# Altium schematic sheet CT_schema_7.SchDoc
size 371 x 245 mm
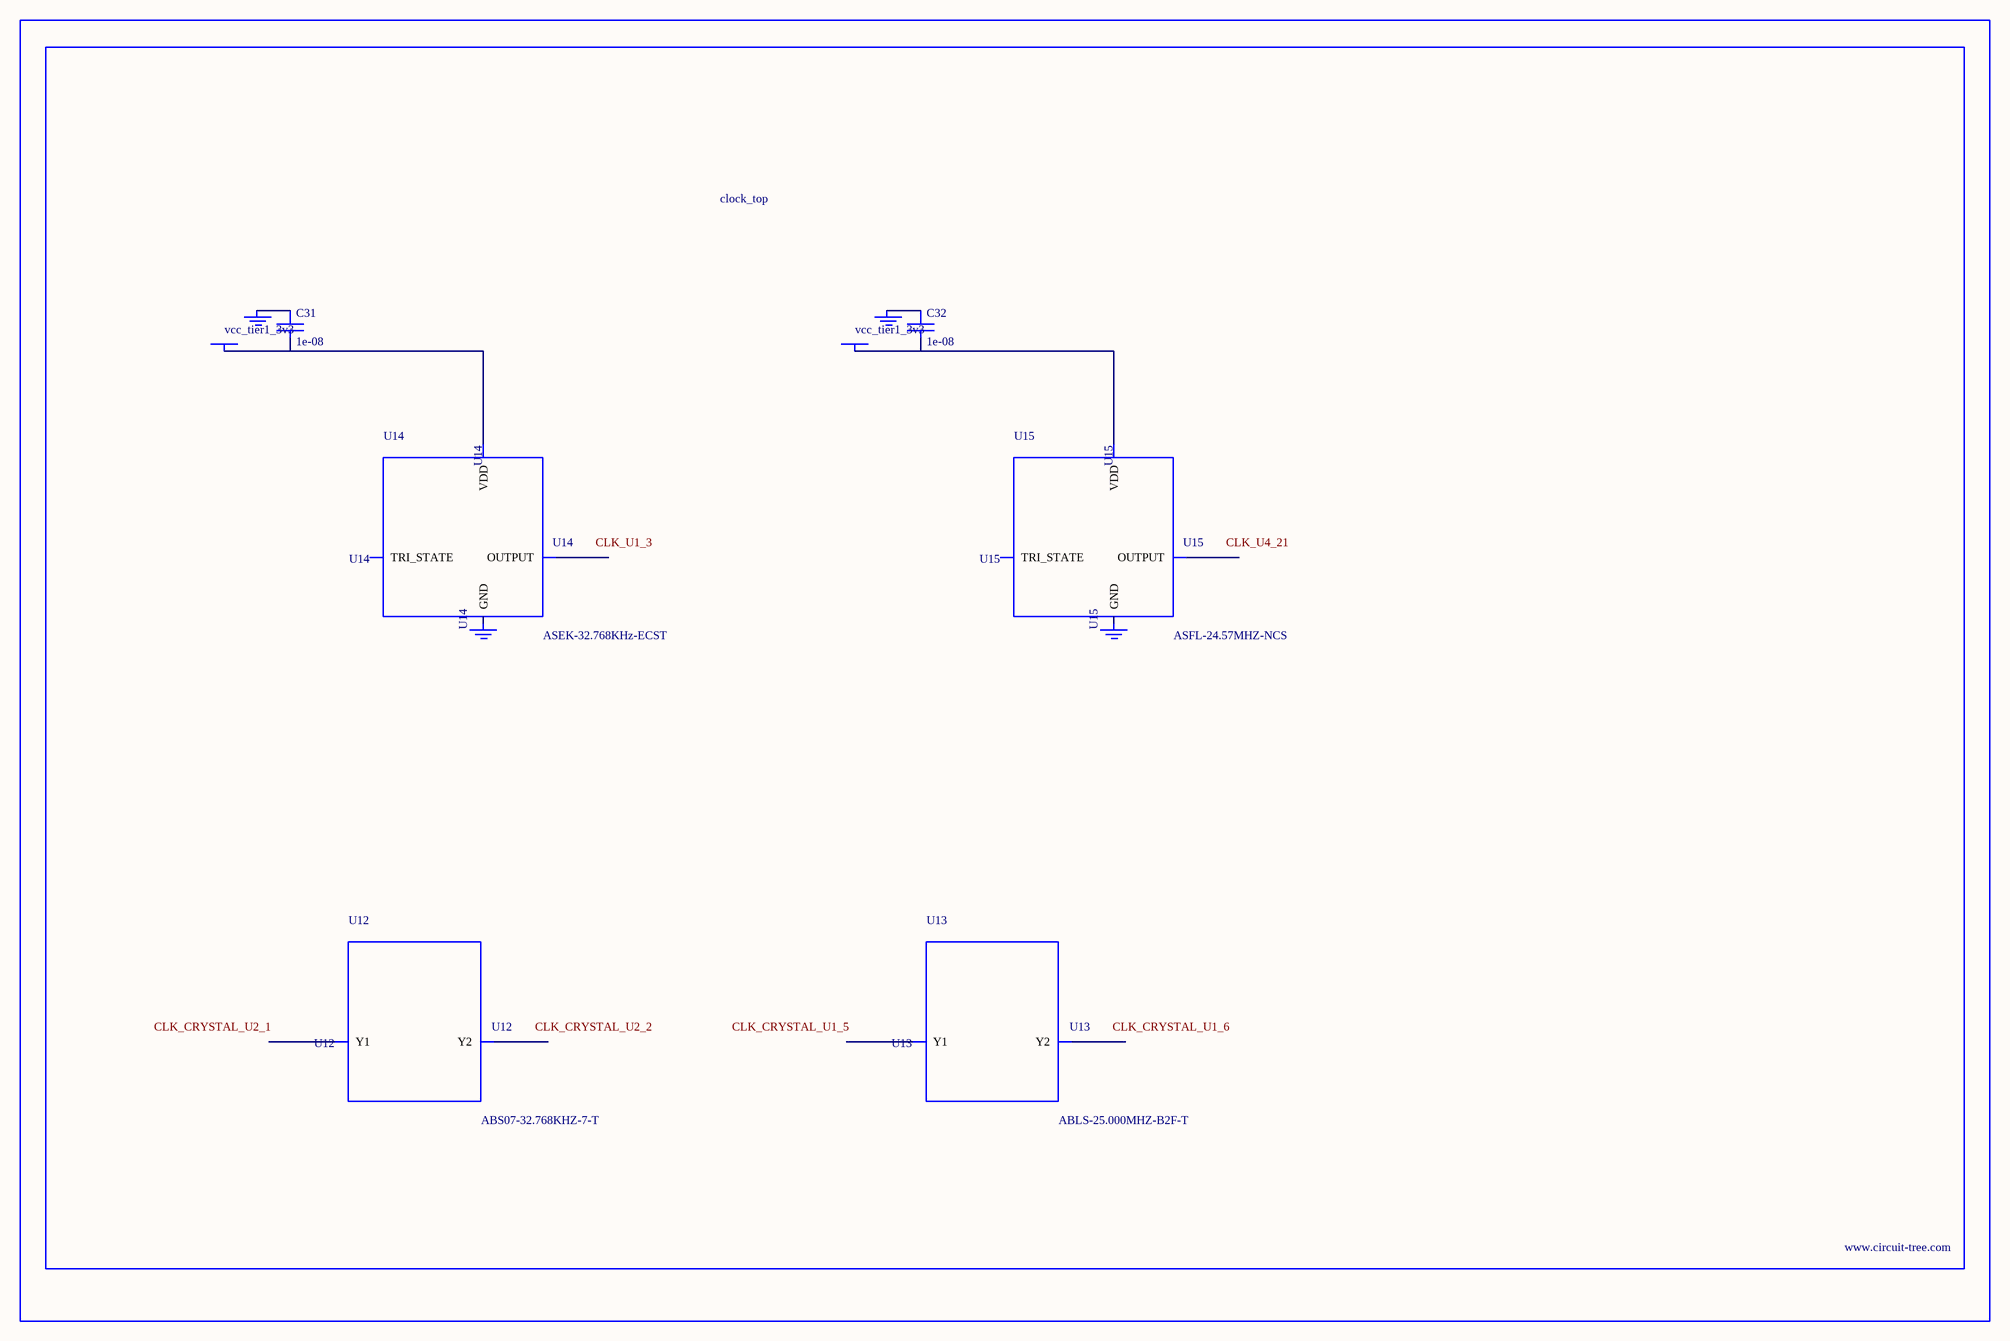
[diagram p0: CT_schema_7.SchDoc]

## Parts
BORDER6  (no value)
C31  1e-08  [C0402]
C32  1e-08  [C0402]
GND_INSTANCE_6_0  (no value)
GND_INSTANCE_6_1  (no value)
GND_INSTANCE_6_2  (no value)
GND_INSTANCE_6_3  (no value)
POWER_INSTANCE_6_0  vcc_tier1_3v3
POWER_INSTANCE_6_1  vcc_tier1_3v3
U12  ABS07-32.768KHZ-7-T  [ABS07-32.768KHZ-7-T]
U13  ABLS-25.000MHZ-B2F-T  [ABLS-25.000MHZ-B2F-T]
U14  ASEK-32.768KHz-ECST  [ASEK]
U15  ASFL-24.57MHZ-NCS  [ASFL1]

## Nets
NetC31_1: C31.1 GND_INSTANCE_6_0.0(GND)
NetC31_2: C31.2 POWER_INSTANCE_6_0.0(PWR) U14.4(VDD)
NetC32_1: C32.1 GND_INSTANCE_6_2.0(GND)
NetC32_2: C32.2 POWER_INSTANCE_6_1.0(PWR) U15.4(VDD)

Not connected (* = marked no-connect by the designer): GND_INSTANCE_6_1 0(GND); GND_INSTANCE_6_3 0(GND); U12 1(Y1) 2(Y2); U13 1(Y1) 2(Y2); U14 1(TRI_STATE) 2(GND) 3(OUTPUT); U15 1(TRI_STATE) 2(GND) 3(OUTPUT)

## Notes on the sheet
- Labels drawn without touching a wire or pin: CLK_CRYSTAL_U1_5, CLK_CRYSTAL_U1_6, CLK_CRYSTAL_U2_1, CLK_CRYSTAL_U2_2, CLK_U1_3, CLK_U4_21

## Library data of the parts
BORDER6 = BORDER_PAGE6
C31 C32 = C0402C103K3RAC
GND_INSTANCE_6_0-GND_INSTANCE_6_3 = GND
POWER_INSTANCE_6_0 POWER_INSTANCE_6_1 = PWR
